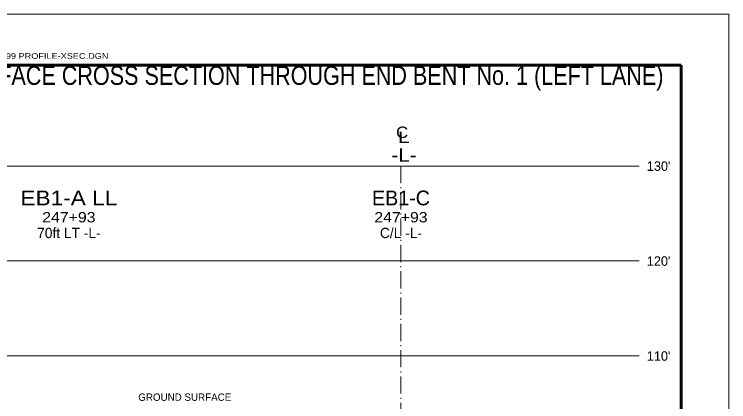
# Model space of a CAD drawing. Extents: x -76 to 974, y -1080 to -735.
# Drawn here: x 281.7 to 357, y -926.9 to -886.1 of the extents above; entities that cross this region are included whole.
import ezdxf
from ezdxf.enums import TextEntityAlignment as Align

# ---------------------------------------------------------------- set-up
doc = ezdxf.new("R2010")
doc.units = 0
doc.header["$LTSCALE"] = 0.36
doc.linetypes.add('DOT_DASHED', pattern=[7.7, 5, -1.2, 0.3, -1.2])
for name, color, linetype, lineweight in [('27', 7, 'Continuous', 40), ('63', 7, 'Continuous', 35), ('7', 7, 'Continuous', 13)]:
    doc.layers.add(name, color=color, linetype=linetype, lineweight=lineweight)

msp = doc.modelspace()

# ---------------------------------------------------------------- linework, layer by layer
at = {"layer": '63', "lineweight": 13}
for p in [(246.9747, -886.1123), (356.9747, -1056.1123)]:
    msp.add_line(p, (356.9747, -886.1123), dxfattribs=at)
at = {"layer": '63', "lineweight": 60}
for q in [(251.9747, -891.4595), (351.9747, -1052.1123)]:
    msp.add_line((351.9747, -891.4595), q, dxfattribs=at)
at = {"layer": '7'}
for p, q in [((256.2421, -902.09), (347.5358, -902.09)), ((256.2421, -912.09), (347.5358, -912.09)), ((256.2421, -922.09), (347.5358, -922.09))]:
    msp.add_line(p, q, dxfattribs=at)
at = {"layer": '7', "linetype": 'DOT_DASHED'}
msp.add_line((322.4355, -902.09), (322.4355, -929.3789), dxfattribs=at)

# ---------------------------------------------------------------- texts
at = {"layer": '27'}
for s, width, p in [('C', 1.1, (321.9193, -899.1407)), ('L', 1.4, (322.1157, -899.6741))]:
    msp.add_text(s, height=1.2, dxfattribs=dict(at, width=width)).set_placement(p)
at = {"layer": '27', "width": 1.15}
for s, height, p in [('-L-', 1.4, (322.762, -901.6327)), ('EB1-A LL', 1.55, (287.4372, -906.2324)), ('247+93', 1.085, (287.438, -908.0288)), ('247+93', 1.085, (322.4381, -908.0288))]:
    msp.add_text(s, height=height, dxfattribs=at).set_placement(p, align=Align.CENTER)
at = {"layer": '27'}
for s, height, p in [('EB1-C', 1.55, (322.4372, -906.2324)), ('70ft LT -L-', 1.085, (287.4375, -909.6858)), ('C/L -L-', 1.085, (322.4376, -909.6858)), ('GROUND SURFACE', 0.7717, (299.652, -926.8202))]:
    msp.add_text(s, height=height, dxfattribs=at).set_placement(p, align=Align.CENTER)
at = {"layer": '63', "width": 1.2}
msp.add_text('S:PROJECTS/2008/08-049/GEOTECH DOT/CADD/R-2719A 198-199 PROFILE-XSEC.DGN', height=0.6, dxfattribs=at).set_placement((251.9582, -890.8007))
at = {"layer": '63', "width": 0.85}
msp.add_text('GENERALIZED SUBSURFACE CROSS SECTION THROUGH END BENT No. 1 (LEFT LANE)', height=2, dxfattribs=at).set_placement((301.9746, -893.5476), align=Align.CENTER)
at = {"layer": '63'}
for s, p in [("130'", (349.5889, -902.6008)), ("120'", (349.5889, -912.6008)), ("110'", (349.589, -922.6008))]:
    msp.add_text(s, height=1, dxfattribs=at).set_placement(p, align=Align.CENTER)

doc.saveas('drawing.dxf')
